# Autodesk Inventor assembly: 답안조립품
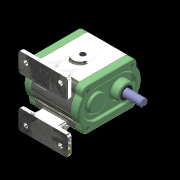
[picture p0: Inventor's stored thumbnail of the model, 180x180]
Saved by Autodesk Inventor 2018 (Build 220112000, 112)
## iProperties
Created: 2023-06
Part Number: 답안조립품
Material: 일반
Document SubType Name: Assembly
Designer: home
Author: home
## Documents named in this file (12)
- C:\Users\home\Desktop\730606V1012\답안조립품.iam
- C:\Users\home\Desktop\730606V1012\본체.ipt
- C:\Users\home\Desktop\730606V1012\뒷커버.ipt
- C:\Users\home\Desktop\730606V1012\앞커버.ipt
- C:\Users\home\Desktop\730606V1012\니들베어링 NA 4902.ipt
- C:\Users\home\Desktop\730606V1012\서브 드라이브 기어.ipt
- C:\Users\home\Desktop\730606V1012\가스켓.ipt
- C:\Users\home\Desktop\730606V1012\메인 드라이브 기어.ipt
- C:\Users\home\Desktop\730606V1012\샤프트.ipt
- C:\Users\home\Desktop\730606V1012\묻힘키 6x6x40.ipt
- C:\Users\home\Desktop\730606V1012\오일실 15 25 7.ipt
- C:\Users\home\Desktop\730606V1012\육각 소켓 머리 볼트 M8 x 100.ipt
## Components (2 placed, 1 different names)
1. 가스켓:1
2. 가스켓:2
